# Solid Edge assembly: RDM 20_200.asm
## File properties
Title: Zylinder
Author: ahadarics
Template: iso metric assembly.asm
Last saved by: ahadarics
Revision: 24
Application: Solid Edge
Username: ahadarics
Dokumentum tartalom típus: 1
Document Number: RDM 20/200
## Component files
Kit_2.par
Profilrohr.par
Kolbenstange.par
Kit_1.par
Mutter_1.par
Mutter_2.par
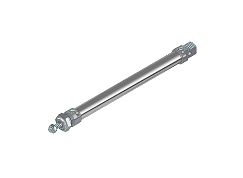
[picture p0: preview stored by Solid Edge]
